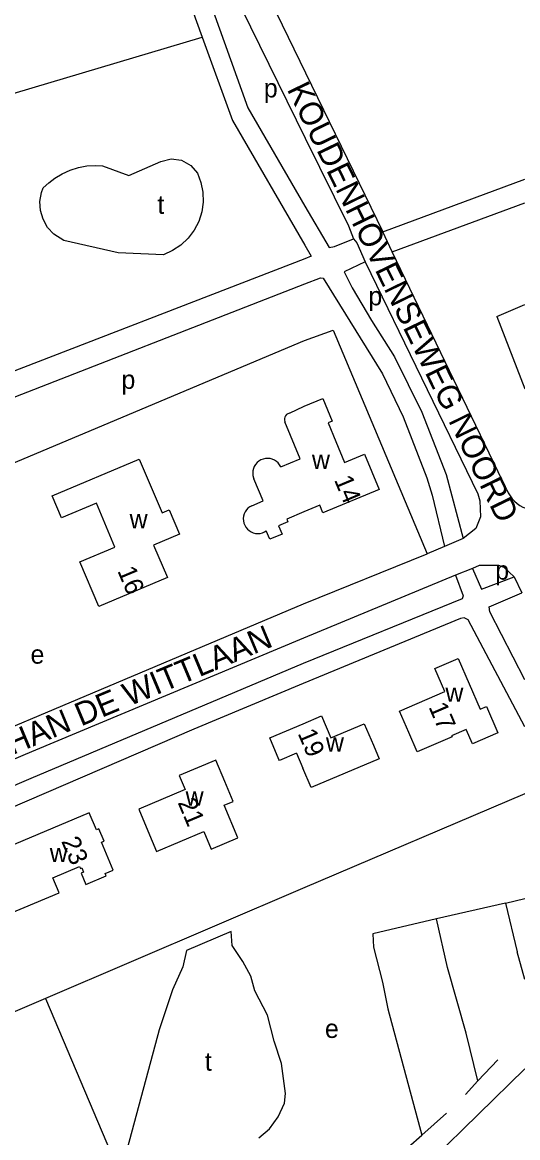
# Model space of a CAD drawing. Extents: x 162427 to 165104, y 384242 to 386287.
# Drawn here: x 163242.2 to 163348.5, y 384850.5 to 385090 of the extents above; entities that cross this region are included whole.
import ezdxf

# ---------------------------------------------------------------- set-up
doc = ezdxf.new("R2010")
doc.units = 0
for name, color, linetype in [('BLT_Basislijn', 7, 'Continuous'), ('BLT_Bebouwing', 7, 'Continuous'), ('BLT_Centroide', 7, 'Continuous'), ('BLT_Huisnummer', 7, 'Continuous'), ('BLT_Straatnaam', 7, 'Continuous')]:
    doc.layers.add(name, color=color, linetype=linetype)

msp = doc.modelspace()

# ---------------------------------------------------------------- linework, layer by layer
at = {"layer": 'BLT_Basislijn'}
for p, q in [((163280.5, 385087.64), (163280.79, 385086.83)), ((163109.64, 385035.76), (163280.79, 385086.83)), ((163319.54, 385045), (163350, 385056.33)), ((163321.58, 385040.73), (163350, 385051.29)), ((163321.58, 385040.73), (163319.54, 385045)), ((163346.18, 384989.63), (163321.58, 385040.73)), ((163343.98, 385026.83), (163350, 385029.4)), ((163343.98, 385026.83), (163350, 385011.33)), ((163332.76, 384977.48), (163329.05, 384975.86)), ((163336.77, 384979.15), (163332.76, 384977.48)), ((163338.77, 384972.73), (163335.15, 384971.31)), ((163347.73, 384970.96), (163349.38, 384967.49)), ((163345.88, 384900.92), (163331.04, 384897.5)), ((163345.88, 384900.92), (163350, 384901.91)), ((163345.88, 384900.92), (163348.41, 384890.46)), ((163333.44, 384887.1), (163331.04, 384897.5)), ((163350, 384884.47), (163348.41, 384890.46)), ((163247.18, 384880.45), (163272.3, 384821.01)), ((163344.2, 384867.27), (163339.97, 384862.71)), ((163337.29, 384859.77), (163339.97, 384862.71)), ((163333.21, 384855.79), (163327.91, 384851.07))]:
    msp.add_line(p, q, dxfattribs=at)
for points in [[(163270.57, 385128.42), (163273.66, 385127.47), (163276.05, 385124.56), (163281.39, 385109.07), (163302.9, 385065.15), (163312.18, 385046.3), (163313.27, 385043.5)], [(163270.57, 385128.42), (163273.36, 385119.85), (163290.61, 385071.64), (163302.84, 385050.56), (163308.02, 385041.68), (163309.2, 385041.87), (163313.27, 385043.5)], [(163266.26, 385128.1), (163267, 385125.19), (163280.5, 385087.64)], [(163280.79, 385086.83), (163287.27, 385068.91), (163302.81, 385042.19), (163304.2, 385039.78), (163302.8, 385039.26), (163232.03, 385011.91), (163174.05, 384994.99), (163139.33, 384982.45), (163094.55, 385037.28), (163050.17, 385099.92)], [(163296.76, 385091.97), (163302.95, 385079.18), (163319.54, 385045)], [(163313.27, 385043.5), (163313.96, 385042.68), (163315.77, 385038.62)], [(163315.77, 385038.62), (163311.27, 385036.46), (163312.99, 385032.98), (163317.12, 385025.96), (163322.02, 385018.21), (163327.9, 385006.28), (163333.15, 384992.92), (163336.77, 384979.15)], [(163315.77, 385038.62), (163339.93, 384988.81), (163340.34, 384987.29), (163340.51, 384983.82), (163339.51, 384981.3), (163336.77, 384979.15)], [(163156.05, 384959.92), (163143.17, 384977.66), (163142.73, 384978.59), (163142.89, 384979), (163176.85, 384991.5), (163234.86, 385007.37), (163302.78, 385033.87), (163306.17, 385035.19), (163306.77, 385035.11), (163319.47, 385014.55), (163323.92, 385005.33), (163328.98, 384992.2), (163330.16, 384988.47), (163332.76, 384977.48)], [(163156.05, 384959.92), (163302.74, 385021.67), (163308.88, 385023.89), (163329.05, 384975.86)], [(163346.18, 384989.63), (163346.48, 384988.96), (163346.85, 384988.32), (163347.29, 384987.73), (163347.79, 384987.19), (163348.35, 384986.71), (163348.95, 384986.29), (163349.6, 384985.93), (163350, 384985.76)], [(163174.52, 384920.17), (163176.12, 384920.16), (163183.37, 384915.07), (163183.91, 384915.07), (163302.53, 384965.17), (163329.05, 384975.86)], [(163347.73, 384970.96), (163345.56, 384972.94), (163344.45, 384973.38), (163340.21, 384973.38), (163338.77, 384972.73)], [(163338.77, 384972.73), (163340.72, 384968.32), (163347.73, 384970.96)], [(163335.15, 384971.31), (163336.81, 384966.89), (163336.59, 384966.26), (163302.48, 384952.34), (163243.99, 384927.63), (163177.81, 384899.17), (163176.54, 384899.27), (163175.78, 384904.36)], [(163335.15, 384971.31), (163302.5, 384957.77), (163244.16, 384933.41), (163175.78, 384904.36)], [(163350, 384948.87), (163342.53, 384963.47), (163342.38, 384964.54), (163349.38, 384967.49)], [(163350, 384938.77), (163337.83, 384961.72), (163337.03, 384962.14), (163336.25, 384962.03), (163302.47, 384948.03), (163279.02, 384938.27), (163179.71, 384895.48)], [(163350, 384924.36), (163302.31, 384904.04), (163247.18, 384880.45)], [(163331.04, 384897.5), (163317.41, 384894.32), (163317.56, 384891.42), (163319.46, 384883.91)], [(163292.96, 384850.5), (163295.22, 384852.43), (163297.07, 384855.03), (163298.43, 384857.97), (163298.63, 384860.02), (163297.78, 384866.45), (163296.26, 384871.26), (163294.77, 384876.83), (163292.1, 384882.03), (163291.22, 384885.19), (163289.53, 384888.33), (163287.25, 384891.77), (163287.03, 384894.78), (163277.44, 384890.7), (163276.61, 384887.22), (163274.45, 384882.25), (163271.58, 384873.7), (163264.76, 384848.44)], [(163339.97, 384862.71), (163337.45, 384872.97), (163333.44, 384887.1)], [(163319.46, 384883.91), (163320.63, 384878.19), (163327.91, 384851.07)], [(163247.18, 384880.45), (163220.86, 384869.18)], [(163343.71, 384838.57), (163331.24, 384833.13), (163330.27, 384833.17), (163328.11, 384839.59), (163328.42, 384843.51), (163330.13, 384845.86), (163350, 384865.28)], [(163312.65, 384840.6), (163318.52, 384843.61), (163322.09, 384845.89), (163327.91, 384851.07)]]:
    msp.add_lwpolyline(points, dxfattribs=at)
msp.add_lwpolyline([(163265.04, 385057.12), (163271.89, 385060.15), (163274.11, 385060.7), (163276.37, 385060.39), (163278.35, 385059.26), (163279.76, 385057.65), (163280.52, 385055.65), (163280.95, 385053.55), (163281.03, 385051.41), (163280.7, 385049.3), (163280.07, 385047.25), (163279.07, 385045.36), (163277.79, 385043.64), (163276.24, 385042.17), (163274.45, 385040.99), (163272.49, 385040.11), (163262.76, 385040.49), (163251.12, 385043.19), (163248.93, 385044.55), (163247.58, 385045.99), (163246.65, 385047.73), (163246.06, 385049.61), (163245.97, 385051.57), (163246.32, 385053.51), (163246.67, 385054.45), (163247.86, 385055.57), (163249.15, 385056.58), (163250.76, 385057.52), (163252.44, 385058.3), (163254.23, 385058.81), (163256.06, 385059.17), (163257.92, 385059.28), (163259.43, 385059.2)], close=True, dxfattribs=at)
at = {"layer": 'BLT_Bebouwing'}
msp.add_line((163301.05, 384933.07), (163302.4, 384929.88), dxfattribs=at)
for points in [[(163299.49, 385006.08), (163302.69, 385007.58), (163306.65, 385009.22), (163308.65, 385004.38), (163307.81, 385004.03), (163309.47, 385000), (163311.32, 384995.52), (163315.61, 384997.29), (163318.76, 384989.68), (163306.71, 384984.7), (163306.05, 384986.31), (163302.6, 384984.89), (163298.92, 384983.37), (163299.18, 384982.74), (163297.18, 384981.92), (163297.92, 384980.12), (163295.27, 384979.03), (163294.52, 384980.83)], [(163297.65, 384994.58), (163301.83, 384996.31), (163298.52, 385004.24)], [(163299.49, 385006.08), (163299.18, 385005.97), (163298.9, 385005.79), (163298.68, 385005.54), (163298.52, 385005.25), (163298.43, 385004.93), (163298.43, 385004.6), (163298.5, 385004.28), (163298.52, 385004.24)], [(163275.9, 384980.11), (163270.37, 384977.78), (163273.31, 384970.78), (163258.58, 384964.58), (163254.54, 384974.18), (163262.05, 384977.34), (163258.09, 384986.76), (163250.58, 384983.59), (163248.57, 384988.36), (163267.3, 384996.22), (163272.17, 384984.67), (163273.71, 384985.32), (163275.9, 384980.11)], [(163297.65, 384994.58), (163297.4, 384995.01), (163297.08, 384995.41), (163296.71, 384995.74), (163296.29, 384996.01), (163295.83, 384996.22), (163295.34, 384996.34), (163294.84, 384996.39), (163294.34, 384996.36), (163293.85, 384996.25), (163293.38, 384996.06), (163292.95, 384995.81), (163292.56, 384995.48), (163292.23, 384995.1), (163291.97, 384994.68), (163291.77, 384994.21), (163291.66, 384993.72), (163291.62, 384993.22), (163291.66, 384992.72), (163291.78, 384992.23), (163291.86, 384992)], [(163291.45, 384986.23), (163293.85, 384987.24), (163291.86, 384992)], [(163291.45, 384986.23), (163291.01, 384985.99), (163290.61, 384985.68), (163290.27, 384985.32), (163289.99, 384984.9), (163289.79, 384984.45), (163289.65, 384983.97), (163289.6, 384983.47), (163289.62, 384982.97), (163289.73, 384982.48), (163289.91, 384982.02), (163290.16, 384981.59), (163290.48, 384981.2), (163290.86, 384980.87), (163291.28, 384980.61), (163291.74, 384980.41), (163292.23, 384980.29), (163292.72, 384980.25), (163293.22, 384980.29), (163293.71, 384980.41), (163294.17, 384980.61), (163294.52, 384980.83)], [(163338.77, 384935.1), (163337.46, 384938.15), (163334.32, 384936.8), (163334.4, 384936.6), (163326.9, 384933.37), (163325.11, 384937.53), (163323.13, 384942.12), (163332.85, 384946.31), (163330.71, 384951.27), (163335.72, 384953.43), (163340.43, 384942.51), (163341.77, 384943.08), (163344.2, 384937.44), (163338.77, 384935.1)], [(163301.05, 384933.07), (163297.35, 384931.5), (163297.24, 384931.76), (163295.28, 384936.36), (163302.44, 384939.4), (163306.41, 384941.09), (163308.41, 384936.38), (163315.57, 384939.42), (163317.53, 384934.82), (163318.77, 384931.9), (163304.18, 384925.7), (163302.4, 384929.88)], [(163281.13, 384916.29), (163282.73, 384912.5), (163288.43, 384914.9), (163285.47, 384921.93), (163287.43, 384922.75), (163285.64, 384927.01), (163283.7, 384931.61), (163275.84, 384928.3), (163277.12, 384925.26), (163267.16, 384921.06), (163269.1, 384916.45), (163270.97, 384912.01), (163281.13, 384916.29)]]:
    msp.add_lwpolyline(points, dxfattribs=at)
msp.add_lwpolyline([(163256.55, 384920.28), (163234.4, 384911.01), (163239.51, 384898.65), (163250.09, 384903.08), (163248.72, 384906.35), (163254.47, 384908.75), (163254.65, 384908.33), (163254.93, 384908.45), (163255.31, 384907.55), (163254.79, 384907.33), (163255.8, 384904.92), (163260.17, 384906.74), (163259.95, 384907.25), (163261.71, 384907.98), (163259.2, 384913.97), (163259.73, 384914.2), (163258.6, 384916.85), (163258.08, 384916.62)], close=True, dxfattribs=at)

# ---------------------------------------------------------------- texts
at = {"layer": 'BLT_Centroide'}
for s, p in [('p', (163294.02, 385073.89)), ('t', (163271.18, 385048.89)), ('p', (163316.45, 385029.25)), ('p', (163263.47, 385011.31)), ('w', (163304.34, 384994.12)), ('w', (163265.22, 384981.36)), ('p', (163343.67, 384970.35)), ('e', (163243.95, 384952.31)), ('w', (163332.98, 384944.12)), ('w', (163307.34, 384933.41)), ('w', (163277.23, 384921.81)), ('w', (163248.07, 384909.69)), ('e', (163307.13, 384871.95)), ('t', (163281.36, 384864.91))]:
    msp.add_text(s, height=4, dxfattribs=at).set_placement(p)
at = {"layer": 'BLT_Huisnummer'}
for s, rotation, p in [('14', 292.6937, (163309.04, 384991.79)), ('16', 292.8203, (163262.54, 384972.26)), ('17', 293.3295, (163329.31, 384943.03)), ('19', 293.0197, (163301.23, 384937.36)), ('21', 292.842, (163275.48, 384922.5)), ('23', 292.7847, (163250.49, 384914.21))]:
    msp.add_text(s, height=4, rotation=rotation, dxfattribs=at).set_placement(p)
at = {"layer": 'BLT_Straatnaam'}
for s, rotation, p in [('KOUDENHOVENSEWEG NOORD', 295.9625, (163298.89, 385075.67)), ('JOHAN DE WITTLAAN', 22.6558, (163232.15, 384929.36))]:
    msp.add_text(s, height=5, rotation=rotation, dxfattribs=at).set_placement(p)

doc.saveas('drawing.dxf')
